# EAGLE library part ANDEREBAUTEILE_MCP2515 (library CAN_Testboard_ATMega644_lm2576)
MC2515 Stand-Alone CAN Controller With SPI Interface
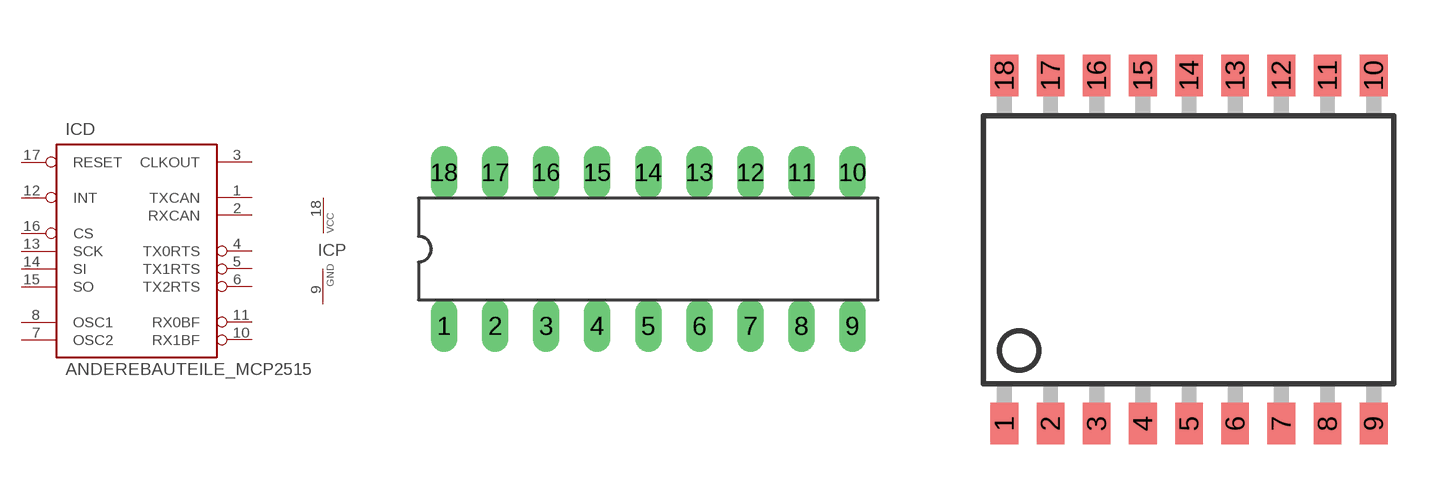
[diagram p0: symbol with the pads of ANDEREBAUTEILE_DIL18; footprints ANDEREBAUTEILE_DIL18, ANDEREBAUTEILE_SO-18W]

Designator prefix IC; gates D=ANDEREBAUTEILE_MCP2515 P=ANDEREBAUTEILE_VCC-GND-1

## ANDEREBAUTEILE_MCP2515P  [ANDEREBAUTEILE_DIL18]
1  D:TXCAN  out
2  D:RXCAN  in
3  D:CLKOUT  out
4  D:TX0RTS  in
5  D:TX1RTS  in
6  D:TX2RTS  in
7  D:OSC2  in
8  D:OSC1  in
9  P:GND  pwr
10  D:RX1BF  out
11  D:RX0BF  out
12  D:INT  out
13  D:SCK  in
14  D:SI  in
15  D:SO  out
16  D:CS  in
17  D:RESET  in
18  P:VCC  pwr

## ANDEREBAUTEILE_MCP2515SO  [ANDEREBAUTEILE_SO-18W]
Pads as for ANDEREBAUTEILE_DIL18

## ANDEREBAUTEILE_MCP2515ST  [ANDEREBAUTEILE_TSSOP20]
1  D:TXCAN  out
2  D:RXCAN  in
3  D:CLKOUT  out
4  D:TX0RTS  in
5  D:TX1RTS  in
7  D:TX2RTS  in
8  D:OSC2  in
9  D:OSC1  in
10  P:GND  pwr
11  D:RX1BF  out
12  D:RX0BF  out
13  D:INT  out
14  D:SCK  in
16  D:SI  in
17  D:SO  out
18  D:CS  in
19  D:RESET  in
20  P:VCC  pwr

## Footprint ANDEREBAUTEILE_DIL18 (pad centres in mm)
Dual In Line package type P
drill 0.813 long: 1 -10.16,-3.81; 2 -7.62,-3.81; 3 -5.08,-3.81; 4 -2.54,-3.81; 5 0,-3.81; 6 2.54,-3.81; 7 5.08,-3.81; 8 7.62,-3.81; 9 10.16,-3.81; 10 10.16,3.81; 11 7.62,3.81; 12 5.08,3.81; 13 2.54,3.81; 14 0,3.81; 15 -2.54,3.81; 16 -5.08,3.81; 17 -7.62,3.81; 18 -10.16,3.81

## Footprint ANDEREBAUTEILE_SO-18W (pad centres in mm)
Small Outline Wide Plastic Gull Wing 300-mil body, package type SO
smd 0.762 x 1.143: 1 -5.08,-4.788; 2 -3.81,-4.788; 3 -2.54,-4.788; 4 -1.27,-4.788; 5 0,-4.788; 6 1.27,-4.788; 7 2.54,-4.788; 8 3.81,-4.788; 9 5.08,-4.788; 10 5.08,4.788; 11 3.81,4.788; 12 2.54,4.788; 13 1.27,4.788; 14 0,4.788; 15 -1.27,4.788; 16 -2.54,4.788; 17 -3.81,4.788; 18 -5.08,4.788

## Footprint ANDEREBAUTEILE_TSSOP20 (pad centres in mm)
Thin Shrink Small Outline Plastic 20 MAX3223-MAX3243.pdf
smd 0.305 x 0.991: 1 -2.925,-2.918; 2 -2.275,-2.918; 3 -1.625,-2.918; 4 -0.975,-2.918; 5 -0.325,-2.918; 6 0.325,-2.918; 7 0.975,-2.918; 8 1.625,-2.918; 9 2.275,-2.918; 10 2.925,-2.918; 11 2.925,2.918; 12 2.275,2.918; 13 1.625,2.918; 14 0.975,2.918; 15 0.325,2.918; 16 -0.325,2.918; 17 -0.975,2.918; 18 -1.625,2.918; 19 -2.275,2.918; 20 -2.925,2.918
